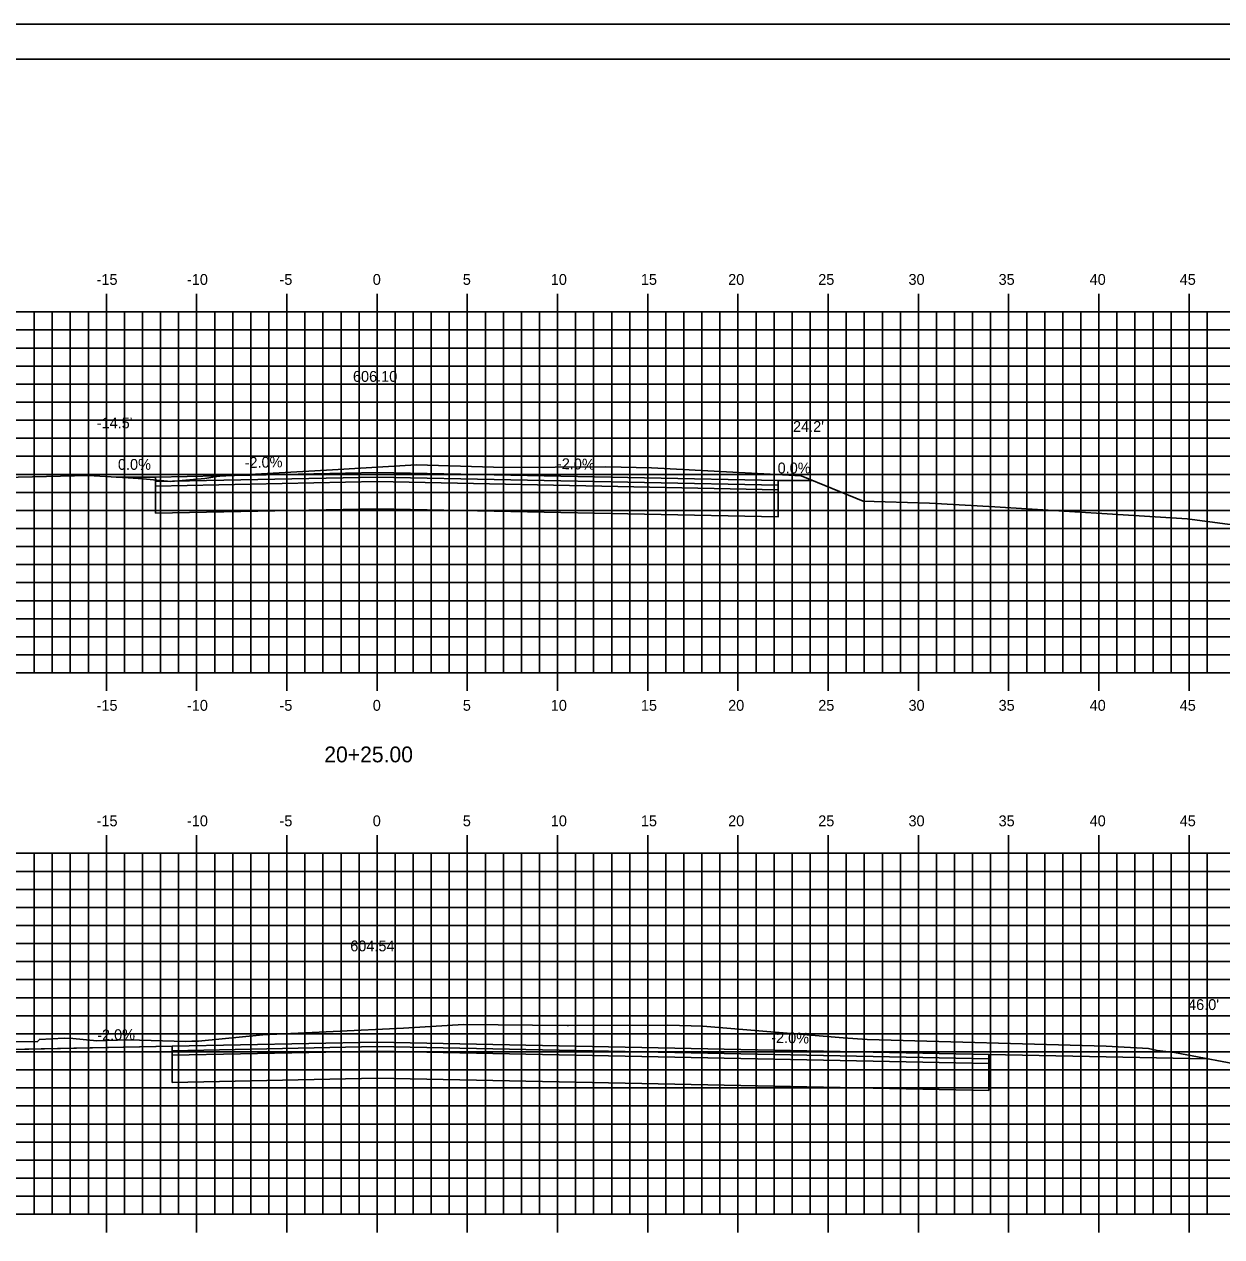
# Model space of a CAD drawing. Extents: x 1048362 to 1048532, y 780904 to 781014.
# Drawn here: x 1048425.9 to 1048492.3, y 780946.9 to 781014.1 of the extents above; entities that cross this region are included whole.
import ezdxf

# ---------------------------------------------------------------- set-up
doc = ezdxf.new("R2010")
doc.units = 0
for name, color, linetype in [('ANNOTATION', 7, 'Continuous'), ('D_Roadway_Centerline', 7, 'Continuous'), ('D_Roadway_Centerline_Text', 7, 'Continuous'), ('D_Roadway_Edge_Pavement', 7, 'Continuous'), ('D_Roadway_Pavement', 7, 'Continuous'), ('D_Roadway_SlopeLines', 7, 'Continuous'), ('D_Roadway_SubGrade', 7, 'Continuous'), ('Default', 7, 'Continuous'), ('H_V ANNOTATION', 7, 'Continuous'), ('MAJOR', 7, 'Continuous'), ('MINOR', 7, 'Continuous'), ('S_Roadway_Centerline', 7, 'Continuous')]:
    doc.layers.add(name, color=color, linetype=linetype)

msp = doc.modelspace()

# ---------------------------------------------------------------- linework, layer by layer
at = {"layer": 'D_Roadway_Centerline'}
for points in [[(1048431.011, 780988.964), (1048433.196, 780988.964), (1048445.469, 780989.21), (1048467.703, 780988.765), (1048469.618, 780988.765)], [(1048416.852, 780957.079), (1048434.112, 780957.424), (1048445.469, 780957.651), (1048479.364, 780956.973), (1048491.458, 780956.731)]]:
    msp.add_lwpolyline(points, dxfattribs=at)
at = {"layer": 'D_Roadway_Edge_Pavement'}
for points in [[(1048433.196, 780988.714), (1048433.196, 780988.964), (1048445.469, 780989.21), (1048467.703, 780988.765), (1048467.703, 780988.515), (1048445.469, 780988.96)], [(1048434.112, 780957.174), (1048434.112, 780957.424), (1048445.469, 780957.651), (1048479.364, 780956.973), (1048479.364, 780956.723), (1048445.469, 780957.401)]]:
    msp.add_lwpolyline(points, close=True, dxfattribs=at)
at = {"layer": 'D_Roadway_Pavement'}
for points in [[(1048433.196, 780988.464), (1048433.196, 780988.714), (1048445.469, 780988.96), (1048467.703, 780988.515), (1048467.703, 780988.265), (1048445.469, 780988.71)], [(1048434.112, 780956.924), (1048434.112, 780957.174), (1048445.469, 780957.401), (1048479.364, 780956.723), (1048479.364, 780956.473), (1048445.469, 780957.151)]]:
    msp.add_lwpolyline(points, close=True, dxfattribs=at)
at = {"layer": 'D_Roadway_SlopeLines'}
for p, q in [((1048434.112, 780957.424), (1048416.852, 780957.079)), ((1048479.364, 780956.973), (1048491.458, 780956.731))]:
    msp.add_line(p, q, dxfattribs=at)
for points in [[(1048433.196, 780988.964), (1048431.011, 780988.964)], [(1048467.703, 780988.765), (1048469.618, 780988.765)]]:
    msp.add_lwpolyline(points, dxfattribs=at)
at = {"layer": 'D_Roadway_SubGrade'}
for points in [[(1048433.196, 780986.964), (1048433.196, 780988.464), (1048445.469, 780988.71), (1048467.703, 780988.265), (1048467.703, 780986.765), (1048445.469, 780987.21)], [(1048434.112, 780955.424), (1048434.112, 780956.924), (1048445.469, 780957.151), (1048479.364, 780956.473), (1048479.364, 780954.973), (1048445.469, 780955.651)]]:
    msp.add_lwpolyline(points, close=True, dxfattribs=at)
at = {"layer": 'Default'}
for p, q in [((1048530.47, 781012.114), (1048370.47, 781012.114)), ((1048479.364, 780956.973), (1048491.458, 780956.731))]:
    msp.add_line(p, q, dxfattribs=at)
msp.add_lwpolyline([(1048362.376, 780904.055), (1048532.376, 780904.055), (1048532.376, 781014.055), (1048362.376, 781014.055)], close=True, dxfattribs=at)
at = {"layer": 'MAJOR'}
for p, q in [((1048430.469, 780999.116), (1048430.469, 780998.114)), ((1048435.469, 780999.116), (1048435.469, 780998.114)), ((1048440.469, 780999.116), (1048440.469, 780998.114)), ((1048445.469, 780999.116), (1048445.469, 780998.114)), ((1048450.469, 780999.116), (1048450.469, 780998.114)), ((1048455.469, 780999.116), (1048455.469, 780998.114)), ((1048460.469, 780999.116), (1048460.469, 780998.114)), ((1048465.469, 780999.116), (1048465.469, 780998.114)), ((1048470.469, 780999.116), (1048470.469, 780998.114)), ((1048475.469, 780999.116), (1048475.469, 780998.114)), ((1048480.469, 780999.116), (1048480.469, 780998.114)), ((1048485.469, 780999.116), (1048485.469, 780998.114)), ((1048490.469, 780999.116), (1048490.469, 780998.114)), ((1048375.469, 780998.114), (1048515.469, 780998.114)), ((1048375.469, 780998.114), (1048515.469, 780998.114)), ((1048430.469, 780978.114), (1048430.469, 780998.114)), ((1048435.469, 780978.114), (1048435.469, 780998.114)), ((1048440.469, 780978.114), (1048440.469, 780998.114)), ((1048445.469, 780978.114), (1048445.469, 780998.114)), ((1048450.469, 780978.114), (1048450.469, 780998.114)), ((1048455.469, 780978.114), (1048455.469, 780998.114)), ((1048460.469, 780978.114), (1048460.469, 780998.114)), ((1048465.469, 780978.114), (1048465.469, 780998.114)), ((1048470.469, 780978.114), (1048470.469, 780998.114)), ((1048475.469, 780978.114), (1048475.469, 780998.114)), ((1048480.469, 780978.114), (1048480.469, 780998.114)), ((1048485.469, 780978.114), (1048485.469, 780998.114)), ((1048490.469, 780978.114), (1048490.469, 780998.114)), ((1048375.469, 780993.114), (1048515.469, 780993.114)), ((1048375.469, 780988.114), (1048515.469, 780988.114)), ((1048375.469, 780983.114), (1048515.469, 780983.114)), ((1048375.469, 780978.114), (1048515.469, 780978.114)), ((1048375.469, 780978.114), (1048515.469, 780978.114)), ((1048430.469, 780977.112), (1048430.469, 780978.114)), ((1048435.469, 780977.112), (1048435.469, 780978.114)), ((1048440.469, 780977.112), (1048440.469, 780978.114)), ((1048445.469, 780977.112), (1048445.469, 780978.114)), ((1048450.469, 780977.112), (1048450.469, 780978.114)), ((1048455.469, 780977.112), (1048455.469, 780978.114)), ((1048460.469, 780977.112), (1048460.469, 780978.114)), ((1048465.469, 780977.112), (1048465.469, 780978.114)), ((1048470.469, 780977.112), (1048470.469, 780978.114)), ((1048475.469, 780977.112), (1048475.469, 780978.114)), ((1048480.469, 780977.112), (1048480.469, 780978.114)), ((1048485.469, 780977.112), (1048485.469, 780978.114)), ((1048490.469, 780977.112), (1048490.469, 780978.114)), ((1048430.469, 780969.116), (1048430.469, 780968.114)), ((1048435.469, 780969.116), (1048435.469, 780968.114)), ((1048440.469, 780969.116), (1048440.469, 780968.114)), ((1048445.469, 780969.116), (1048445.469, 780968.114)), ((1048450.469, 780969.116), (1048450.469, 780968.114)), ((1048455.469, 780969.116), (1048455.469, 780968.114)), ((1048460.469, 780969.116), (1048460.469, 780968.114)), ((1048465.469, 780969.116), (1048465.469, 780968.114)), ((1048470.469, 780969.116), (1048470.469, 780968.114)), ((1048475.469, 780969.116), (1048475.469, 780968.114)), ((1048480.469, 780969.116), (1048480.469, 780968.114)), ((1048485.469, 780969.116), (1048485.469, 780968.114)), ((1048490.469, 780969.116), (1048490.469, 780968.114)), ((1048375.469, 780968.114), (1048515.469, 780968.114)), ((1048375.469, 780968.114), (1048515.469, 780968.114)), ((1048430.469, 780948.114), (1048430.469, 780968.114)), ((1048435.469, 780948.114), (1048435.469, 780968.114)), ((1048440.469, 780948.114), (1048440.469, 780968.114)), ((1048445.469, 780948.114), (1048445.469, 780968.114)), ((1048450.469, 780948.114), (1048450.469, 780968.114)), ((1048455.469, 780948.114), (1048455.469, 780968.114)), ((1048460.469, 780948.114), (1048460.469, 780968.114)), ((1048465.469, 780948.114), (1048465.469, 780968.114)), ((1048470.469, 780948.114), (1048470.469, 780968.114)), ((1048475.469, 780948.114), (1048475.469, 780968.114)), ((1048480.469, 780948.114), (1048480.469, 780968.114)), ((1048485.469, 780948.114), (1048485.469, 780968.114)), ((1048490.469, 780948.114), (1048490.469, 780968.114)), ((1048375.469, 780963.114), (1048515.469, 780963.114)), ((1048375.469, 780958.114), (1048515.469, 780958.114)), ((1048375.469, 780953.114), (1048515.469, 780953.114)), ((1048375.469, 780948.114), (1048515.469, 780948.114)), ((1048375.469, 780948.114), (1048515.469, 780948.114)), ((1048430.469, 780947.112), (1048430.469, 780948.114)), ((1048435.469, 780947.112), (1048435.469, 780948.114)), ((1048440.469, 780947.112), (1048440.469, 780948.114)), ((1048445.469, 780947.112), (1048445.469, 780948.114)), ((1048450.469, 780947.112), (1048450.469, 780948.114)), ((1048455.469, 780947.112), (1048455.469, 780948.114)), ((1048460.469, 780947.112), (1048460.469, 780948.114)), ((1048465.469, 780947.112), (1048465.469, 780948.114)), ((1048470.469, 780947.112), (1048470.469, 780948.114)), ((1048475.469, 780947.112), (1048475.469, 780948.114)), ((1048480.469, 780947.112), (1048480.469, 780948.114)), ((1048485.469, 780947.112), (1048485.469, 780948.114)), ((1048490.469, 780947.112), (1048490.469, 780948.114))]:
    msp.add_line(p, q, dxfattribs=at)
at = {"layer": 'MINOR'}
for p, q in [((1048426.469, 780978.114), (1048426.469, 780998.114)), ((1048427.469, 780978.114), (1048427.469, 780998.114)), ((1048428.469, 780978.114), (1048428.469, 780998.114)), ((1048429.469, 780978.114), (1048429.469, 780998.114)), ((1048431.469, 780978.114), (1048431.469, 780998.114)), ((1048432.469, 780978.114), (1048432.469, 780998.114)), ((1048433.469, 780978.114), (1048433.469, 780998.114)), ((1048434.469, 780978.114), (1048434.469, 780998.114)), ((1048436.469, 780978.114), (1048436.469, 780998.114)), ((1048437.469, 780978.114), (1048437.469, 780998.114)), ((1048438.469, 780978.114), (1048438.469, 780998.114)), ((1048439.469, 780978.114), (1048439.469, 780998.114)), ((1048441.469, 780978.114), (1048441.469, 780998.114)), ((1048442.469, 780978.114), (1048442.469, 780998.114)), ((1048443.469, 780978.114), (1048443.469, 780998.114)), ((1048444.469, 780978.114), (1048444.469, 780998.114)), ((1048446.469, 780978.114), (1048446.469, 780998.114)), ((1048447.469, 780978.114), (1048447.469, 780998.114)), ((1048448.469, 780978.114), (1048448.469, 780998.114)), ((1048449.469, 780978.114), (1048449.469, 780998.114)), ((1048451.469, 780978.114), (1048451.469, 780998.114)), ((1048452.469, 780978.114), (1048452.469, 780998.114)), ((1048453.469, 780978.114), (1048453.469, 780998.114)), ((1048454.469, 780978.114), (1048454.469, 780998.114)), ((1048456.469, 780978.114), (1048456.469, 780998.114)), ((1048457.469, 780978.114), (1048457.469, 780998.114)), ((1048458.469, 780978.114), (1048458.469, 780998.114)), ((1048459.469, 780978.114), (1048459.469, 780998.114)), ((1048461.469, 780978.114), (1048461.469, 780998.114)), ((1048462.469, 780978.114), (1048462.469, 780998.114)), ((1048463.469, 780978.114), (1048463.469, 780998.114)), ((1048464.469, 780978.114), (1048464.469, 780998.114)), ((1048466.469, 780978.114), (1048466.469, 780998.114)), ((1048467.469, 780978.114), (1048467.469, 780998.114)), ((1048468.469, 780978.114), (1048468.469, 780998.114)), ((1048469.469, 780978.114), (1048469.469, 780998.114)), ((1048471.469, 780978.114), (1048471.469, 780998.114)), ((1048472.469, 780978.114), (1048472.469, 780998.114)), ((1048473.469, 780978.114), (1048473.469, 780998.114)), ((1048474.469, 780978.114), (1048474.469, 780998.114)), ((1048476.469, 780978.114), (1048476.469, 780998.114)), ((1048477.469, 780978.114), (1048477.469, 780998.114)), ((1048478.469, 780978.114), (1048478.469, 780998.114)), ((1048479.469, 780978.114), (1048479.469, 780998.114)), ((1048481.469, 780978.114), (1048481.469, 780998.114)), ((1048482.469, 780978.114), (1048482.469, 780998.114)), ((1048483.469, 780978.114), (1048483.469, 780998.114)), ((1048484.469, 780978.114), (1048484.469, 780998.114)), ((1048486.469, 780978.114), (1048486.469, 780998.114)), ((1048487.469, 780978.114), (1048487.469, 780998.114)), ((1048488.469, 780978.114), (1048488.469, 780998.114)), ((1048489.469, 780978.114), (1048489.469, 780998.114)), ((1048491.469, 780978.114), (1048491.469, 780998.114)), ((1048375.469, 780997.114), (1048515.469, 780997.114)), ((1048375.469, 780996.114), (1048515.469, 780996.114)), ((1048375.469, 780995.114), (1048515.469, 780995.114)), ((1048375.469, 780994.114), (1048515.469, 780994.114)), ((1048375.469, 780992.114), (1048515.469, 780992.114)), ((1048375.469, 780991.114), (1048515.469, 780991.114)), ((1048375.469, 780990.114), (1048515.469, 780990.114)), ((1048375.469, 780989.114), (1048515.469, 780989.114)), ((1048375.469, 780987.114), (1048515.469, 780987.114)), ((1048375.469, 780986.114), (1048515.469, 780986.114)), ((1048375.469, 780985.114), (1048515.469, 780985.114)), ((1048375.469, 780984.114), (1048515.469, 780984.114)), ((1048375.469, 780982.114), (1048515.469, 780982.114)), ((1048375.469, 780981.114), (1048515.469, 780981.114)), ((1048375.469, 780980.114), (1048515.469, 780980.114)), ((1048375.469, 780979.114), (1048515.469, 780979.114)), ((1048426.469, 780948.114), (1048426.469, 780968.114)), ((1048427.469, 780948.114), (1048427.469, 780968.114)), ((1048428.469, 780948.114), (1048428.469, 780968.114)), ((1048429.469, 780948.114), (1048429.469, 780968.114)), ((1048431.469, 780948.114), (1048431.469, 780968.114)), ((1048432.469, 780948.114), (1048432.469, 780968.114)), ((1048433.469, 780948.114), (1048433.469, 780968.114)), ((1048434.469, 780948.114), (1048434.469, 780968.114)), ((1048436.469, 780948.114), (1048436.469, 780968.114)), ((1048437.469, 780948.114), (1048437.469, 780968.114)), ((1048438.469, 780948.114), (1048438.469, 780968.114)), ((1048439.469, 780948.114), (1048439.469, 780968.114)), ((1048441.469, 780948.114), (1048441.469, 780968.114)), ((1048442.469, 780948.114), (1048442.469, 780968.114)), ((1048443.469, 780948.114), (1048443.469, 780968.114)), ((1048444.469, 780948.114), (1048444.469, 780968.114)), ((1048446.469, 780948.114), (1048446.469, 780968.114)), ((1048447.469, 780948.114), (1048447.469, 780968.114)), ((1048448.469, 780948.114), (1048448.469, 780968.114)), ((1048449.469, 780948.114), (1048449.469, 780968.114)), ((1048451.469, 780948.114), (1048451.469, 780968.114)), ((1048452.469, 780948.114), (1048452.469, 780968.114)), ((1048453.469, 780948.114), (1048453.469, 780968.114)), ((1048454.469, 780948.114), (1048454.469, 780968.114)), ((1048456.469, 780948.114), (1048456.469, 780968.114)), ((1048457.469, 780948.114), (1048457.469, 780968.114)), ((1048458.469, 780948.114), (1048458.469, 780968.114)), ((1048459.469, 780948.114), (1048459.469, 780968.114)), ((1048461.469, 780948.114), (1048461.469, 780968.114)), ((1048462.469, 780948.114), (1048462.469, 780968.114)), ((1048463.469, 780948.114), (1048463.469, 780968.114)), ((1048464.469, 780948.114), (1048464.469, 780968.114)), ((1048466.469, 780948.114), (1048466.469, 780968.114)), ((1048467.469, 780948.114), (1048467.469, 780968.114)), ((1048468.469, 780948.114), (1048468.469, 780968.114)), ((1048469.469, 780948.114), (1048469.469, 780968.114)), ((1048471.469, 780948.114), (1048471.469, 780968.114)), ((1048472.469, 780948.114), (1048472.469, 780968.114)), ((1048473.469, 780948.114), (1048473.469, 780968.114)), ((1048474.469, 780948.114), (1048474.469, 780968.114)), ((1048476.469, 780948.114), (1048476.469, 780968.114)), ((1048477.469, 780948.114), (1048477.469, 780968.114)), ((1048478.469, 780948.114), (1048478.469, 780968.114)), ((1048479.469, 780948.114), (1048479.469, 780968.114)), ((1048481.469, 780948.114), (1048481.469, 780968.114)), ((1048482.469, 780948.114), (1048482.469, 780968.114)), ((1048483.469, 780948.114), (1048483.469, 780968.114)), ((1048484.469, 780948.114), (1048484.469, 780968.114)), ((1048486.469, 780948.114), (1048486.469, 780968.114)), ((1048487.469, 780948.114), (1048487.469, 780968.114)), ((1048488.469, 780948.114), (1048488.469, 780968.114)), ((1048489.469, 780948.114), (1048489.469, 780968.114)), ((1048491.469, 780948.114), (1048491.469, 780968.114)), ((1048375.469, 780967.114), (1048515.469, 780967.114)), ((1048375.469, 780966.114), (1048515.469, 780966.114)), ((1048375.469, 780965.114), (1048515.469, 780965.114)), ((1048375.469, 780964.114), (1048515.469, 780964.114)), ((1048375.469, 780962.114), (1048515.469, 780962.114)), ((1048375.469, 780961.114), (1048515.469, 780961.114)), ((1048375.469, 780960.114), (1048515.469, 780960.114)), ((1048375.469, 780959.114), (1048515.469, 780959.114)), ((1048375.469, 780957.114), (1048515.469, 780957.114)), ((1048375.469, 780956.114), (1048515.469, 780956.114)), ((1048375.469, 780955.114), (1048515.469, 780955.114)), ((1048375.469, 780954.114), (1048515.469, 780954.114)), ((1048375.469, 780952.114), (1048515.469, 780952.114)), ((1048375.469, 780951.114), (1048515.469, 780951.114)), ((1048375.469, 780950.114), (1048515.469, 780950.114)), ((1048375.469, 780949.114), (1048515.469, 780949.114))]:
    msp.add_line(p, q, dxfattribs=at)
at = {"layer": 'S_Roadway_Centerline'}
for points in [[(1048422.46, 780988.888), (1048429.469, 780989.042), (1048431.683, 780988.93), (1048432.503, 780988.86), (1048434.037, 780988.719), (1048435.915, 780988.883), (1048436.697, 780989.006), (1048436.755, 780989.005), (1048442.99, 780989.373), (1048447.66, 780989.639), (1048452.523, 780989.5), (1048458.14, 780989.526), (1048460.67, 780989.466), (1048463.798, 780989.309), (1048468.977, 780989.026), (1048472.406, 780987.632), (1048476.081, 780987.522), (1048479.697, 780987.307), (1048490.358, 780986.648), (1048503.356, 780984.928), (1048505.12, 780984.938), (1048511.821, 780984.344), (1048515.469, 780983.985)], [(1048420.632, 780957.738), (1048426.629, 780957.671), (1048426.753, 780957.801), (1048428.126, 780957.864), (1048428.612, 780957.848), (1048429.94, 780957.729), (1048431.661, 780957.776), (1048434.864, 780957.68), (1048435.201, 780957.71), (1048435.574, 780957.704), (1048439.141, 780958.054), (1048446.93, 780958.434), (1048450.251, 780958.631), (1048455.994, 780958.571), (1048456.069, 780958.57), (1048461.575, 780958.591), (1048463.523, 780958.542), (1048471.302, 780957.886), (1048472.634, 780957.802), (1048485.867, 780957.431), (1048488.218, 780957.307), (1048488.695, 780957.191), (1048489.666, 780957.071), (1048493.958, 780956.257)]]:
    msp.add_lwpolyline(points, dxfattribs=at)

# ---------------------------------------------------------------- texts
at = {"layer": 'ANNOTATION'}
for s, rotation, p in [("-14.5'", 360, (1048429.933, 780991.664)), ("24.2'", 360, (1048468.519, 780991.465)), ('-2.0%', 1.14576, (1048438.136, 780989.463)), ('-2.0%', 358.85424, (1048455.429, 780989.411)), ("46.0'", 360, (1048490.412, 780959.431)), ('-2.0%', 1.14576, (1048429.964, 780957.741)), ('-2.0%', 358.85424, (1048467.307, 780957.614))]:
    msp.add_text(s, height=0.6, rotation=rotation, dxfattribs=at).set_placement(p)
for p in [(1048431.108, 780989.364), (1048467.666, 780989.165)]:
    msp.add_text('0.0%', height=0.6, dxfattribs=at).set_placement(p)
at = {"layer": 'D_Roadway_Centerline_Text'}
for s, p in [('606.10', (1048444.132, 780994.242)), ('604.54', (1048443.982, 780962.683))]:
    msp.add_text(s, height=0.6, dxfattribs=at).set_placement(p)
at = {"layer": 'H_V ANNOTATION'}
for s, height, p in [('-15', 0.6, (1048429.926, 780999.614)), ('-10', 0.6, (1048434.934, 780999.614)), ('-5', 0.6, (1048440.06, 780999.614)), ('0', 0.6, (1048445.229, 780999.614)), ('5', 0.6, (1048450.221, 780999.614)), ('10', 0.6, (1048455.095, 780999.614)), ('15', 0.6, (1048460.087, 780999.614)), ('20', 0.6, (1048464.923, 780999.614)), ('25', 0.6, (1048469.915, 780999.614)), ('30', 0.6, (1048474.918, 780999.614)), ('35', 0.6, (1048479.91, 780999.614)), ('40', 0.6, (1048484.956, 780999.614)), ('45', 0.6, (1048489.948, 780999.614)), ('-15', 0.6, (1048429.926, 780976.014)), ('-10', 0.6, (1048434.934, 780976.014)), ('-5', 0.6, (1048440.06, 780976.014)), ('0', 0.6, (1048445.229, 780976.014)), ('5', 0.6, (1048450.221, 780976.014)), ('10', 0.6, (1048455.095, 780976.014)), ('15', 0.6, (1048460.087, 780976.014)), ('20', 0.6, (1048464.923, 780976.014)), ('25', 0.6, (1048469.915, 780976.014)), ('30', 0.6, (1048474.918, 780976.014)), ('35', 0.6, (1048479.91, 780976.014)), ('40', 0.6, (1048484.956, 780976.014)), ('45', 0.6, (1048489.948, 780976.014)), ('20+25.00', 0.875, (1048442.543, 780973.157)), ('-15', 0.6, (1048429.926, 780969.614)), ('-10', 0.6, (1048434.934, 780969.614)), ('-5', 0.6, (1048440.06, 780969.614)), ('0', 0.6, (1048445.229, 780969.614)), ('5', 0.6, (1048450.221, 780969.614)), ('10', 0.6, (1048455.095, 780969.614)), ('15', 0.6, (1048460.087, 780969.614)), ('20', 0.6, (1048464.923, 780969.614)), ('25', 0.6, (1048469.915, 780969.614)), ('30', 0.6, (1048474.918, 780969.614)), ('35', 0.6, (1048479.91, 780969.614)), ('40', 0.6, (1048484.956, 780969.614)), ('45', 0.6, (1048489.948, 780969.614))]:
    msp.add_text(s, height=height, dxfattribs=at).set_placement(p)
at = {"layer": 'S_Roadway_Centerline'}
for s, p in [('C', (1048447.655, 780989.639)), ('L', (1048447.66, 780989.632)), ('C', (1048450.246, 780958.631)), ('L', (1048450.251, 780958.623))]:
    msp.add_text(s, height=0.0146, dxfattribs=at).set_placement(p)

doc.saveas('drawing.dxf')
